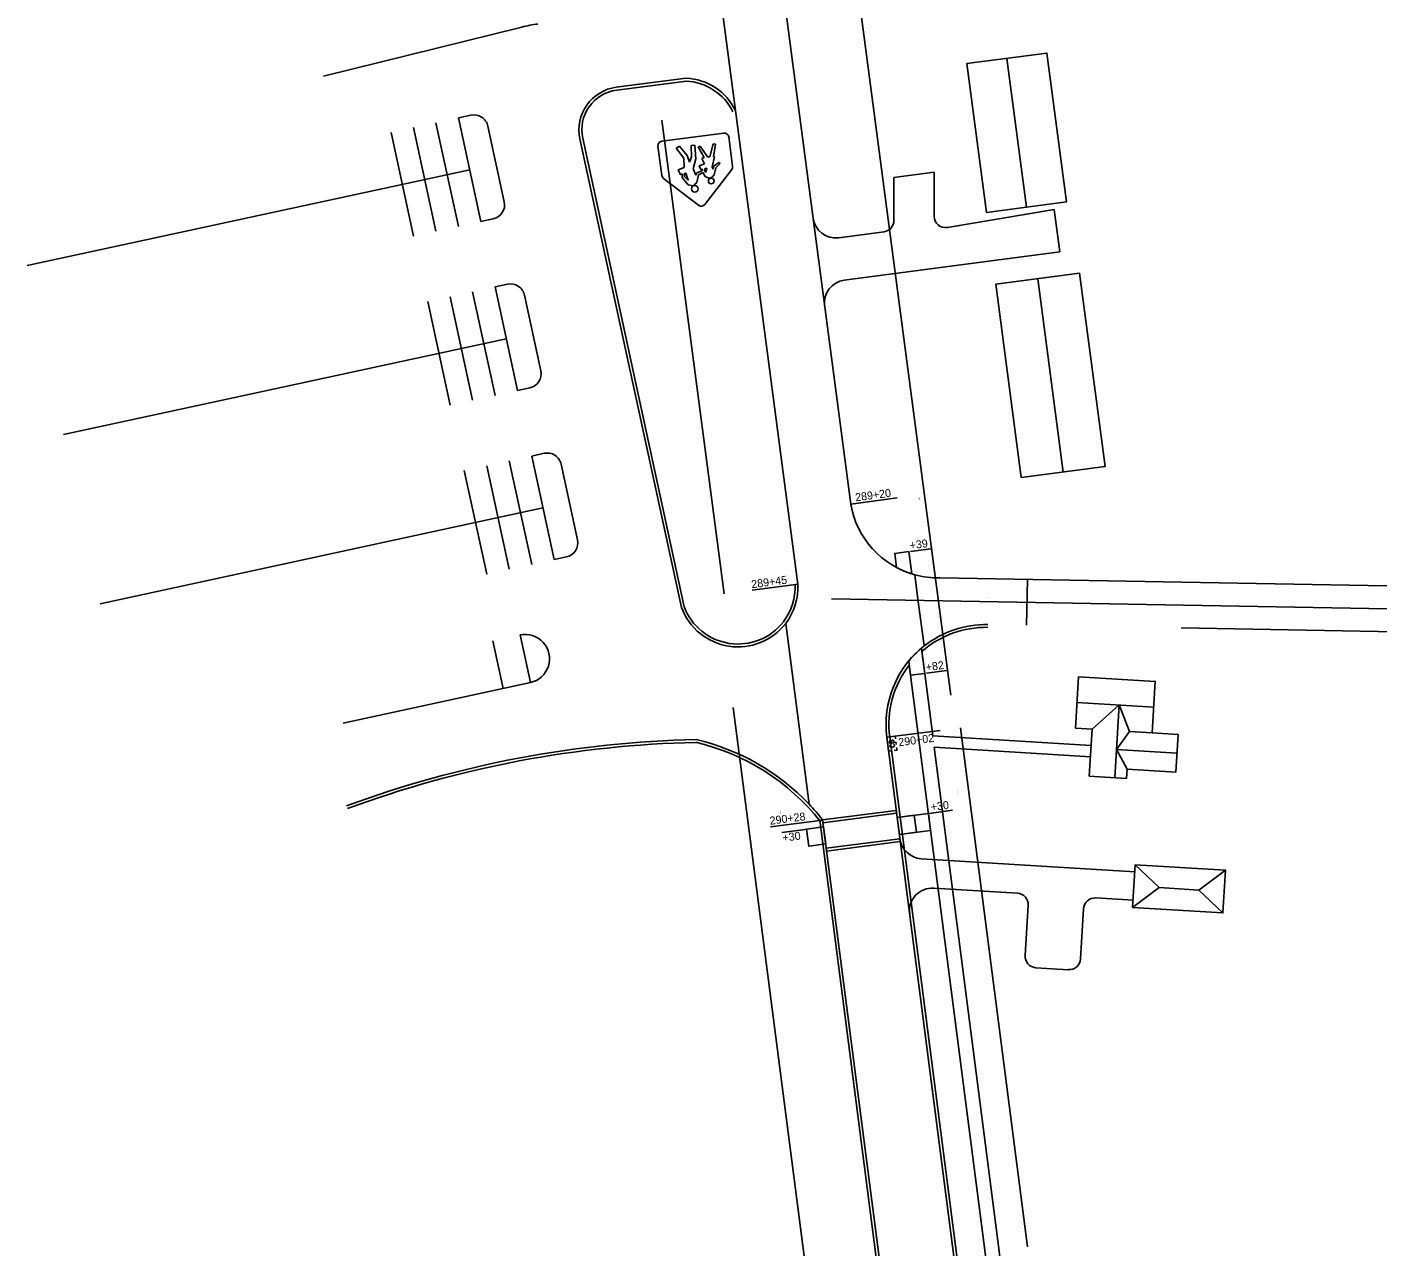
# Model space of a CAD drawing. Extents: x 107766 to 4387554, y 20109 to 1193017.
# Drawn here: x 1746574.1 to 1747046.9, y 281751.5 to 282178.4 of the extents above; entities that cross this region are included whole.
import ezdxf

# ---------------------------------------------------------------- set-up
doc = ezdxf.new("R2010")
doc.units = 0
for name, color, linetype in [('GM_X_Corporation', 7, 'Continuous'), ('GM_X_County_Road', 7, 'Continuous'), ('GM_X_State_Route', 7, 'Continuous'), ('GM_X_Township', 7, 'Continuous'), ('GM_X_US_Route', 7, 'Continuous'), ('GM_X_US_Shield', 7, 'Continuous'), ('Level 60', 7, 'Continuous'), ('Level 62', 7, 'Continuous'), ('RD_P_Text', 7, 'Continuous'), ('SC_Scratch1', 7, 'Continuous'), ('SC_Scratch10', 7, 'Continuous'), ('SC_Scratch5', 7, 'Continuous'), ('SC_Scratch8', 7, 'Continuous'), ('SH_Data', 7, 'Continuous')]:
    doc.layers.add(name, color=color, linetype=linetype)

msp = doc.modelspace()

# ---------------------------------------------------------------- linework, layer by layer
at = {"layer": 'GM_X_Corporation'}
for p, q in [((1746876.04, 281930.01), (1746875.06, 281929.89)), ((1746875.19, 281928.91), (1746875.06, 281929.89)), ((1746877.99, 281930.26), (1746877.01, 281930.14)), ((1746878.11, 281929.29), (1746877.99, 281930.26)), ((1746875.44, 281926.96), (1746875.31, 281927.93)), ((1746875.69, 281925.01), (1746875.56, 281925.98)), ((1746876.67, 281925.13), (1746875.69, 281925.01)), ((1746876.75, 281927.89), (1746876.67, 281928.58)), ((1746876.84, 281927.64), (1746876.84, 281927.64)), ((1746878.62, 281925.38), (1746877.64, 281925.26)), ((1746878.37, 281927.34), (1746878.24, 281928.31)), ((1746878.62, 281925.38), (1746878.49, 281926.36))]:
    msp.add_line(p, q, dxfattribs=at)
msp.add_lwpolyline([(1746875.96, 281928.42), (1746876.04, 281927.8), (1746877.61, 281928), (1746877.52, 281928.69)], dxfattribs=at)
for centre, radius, start, end in [((1746876.35, 281928.36), 0.388, 34.1764, 170.357), ((1746876.64, 281926.88), 0.5, 118.916, 255.7954), ((1746876.77, 281928.18), 1.8, 262.1664, 292.545), ((1746877.11, 281928.46), 0.462, 29.4104, 165.301), ((1746877.22, 281926.95), 0.5, 298.916, 75.7954)]:
    msp.add_arc(centre, radius, start, end, dxfattribs=at)
at = {"layer": 'GM_X_County_Road'}
for p, q in [((1746796.31, 282138.46), (1746818, 282141.31)), ((1746813.13, 282133.02), (1746814.32, 282137.58)), ((1746814.32, 282137.58), (1746815.08, 282137.46)), ((1746819.75, 282139.97), (1746821.09, 282129.77)), ((1746796.3, 282126.5), (1746794.96, 282136.71)), ((1746801.36, 282135.99), (1746802.48, 282136.7)), ((1746803.98, 282132.49), (1746801.36, 282135.99)), ((1746802.48, 282136.7), (1746805.12, 282133.43)), ((1746805.12, 282133.43), (1746806.05, 282131.18)), ((1746806.05, 282131.18), (1746806.66, 282132.96)), ((1746806.6, 282137.02), (1746807.86, 282137.07)), ((1746806.66, 282132.96), (1746806.6, 282137.02)), ((1746807.86, 282137.07), (1746808.23, 282132.26)), ((1746809.08, 282136.55), (1746809.69, 282136.75)), ((1746811.11, 282132.75), (1746809.08, 282136.55)), ((1746809.69, 282136.75), (1746812.24, 282133.01)), ((1746812.24, 282133.01), (1746813.13, 282133.02)), ((1746814.72, 282133), (1746813.91, 282129.5)), ((1746815.08, 282137.46), (1746814.34, 282133.06)), ((1746814.34, 282133.06), (1746814.72, 282133)), ((1746802.03, 282128.51), (1746804.14, 282129.24)), ((1746802.9, 282126.7), (1746802.03, 282128.51)), ((1746804.14, 282129.24), (1746803.98, 282132.49)), ((1746808.23, 282132.26), (1746807.3, 282128.86)), ((1746807.3, 282128.86), (1746808.18, 282126.61)), ((1746808.59, 282127.45), (1746810.35, 282128.13)), ((1746809.38, 282129.92), (1746811.25, 282130.51)), ((1746809.98, 282128.54), (1746809.38, 282129.92)), ((1746810.54, 282128.72), (1746809.98, 282128.54)), ((1746810.26, 282132.41), (1746811.11, 282132.75)), ((1746811.25, 282130.51), (1746810.26, 282132.41)), ((1746810.35, 282128.13), (1746810.54, 282128.72)), ((1746811.46, 282128.96), (1746811.23, 282128.25)), ((1746811.23, 282128.25), (1746811.7, 282127.52)), ((1746820.78, 282128.61), (1746811.37, 282116.34)), ((1746812.08, 282129.04), (1746811.46, 282128.96)), ((1746811.7, 282127.52), (1746812.08, 282129.04)), ((1746813.91, 282129.5), (1746814.29, 282128.65)), ((1746814.29, 282128.65), (1746814.52, 282129.7)), ((1746814.52, 282129.7), (1746816.24, 282131.05)), ((1746815.23, 282129.12), (1746814.65, 282126.66)), ((1746816.76, 282130.67), (1746815.23, 282129.12)), ((1746816.24, 282131.05), (1746816.76, 282130.67)), ((1746809.17, 282116.05), (1746796.9, 282125.47)), ((1746803.54, 282127.01), (1746802.9, 282126.7)), ((1746803.39, 282125.75), (1746803.54, 282127.01)), ((1746805.57, 282123.21), (1746803.39, 282125.75)), ((1746804.24, 282126.09), (1746804.25, 282127.21)), ((1746805.56, 282124.9), (1746804.24, 282126.09)), ((1746804.25, 282127.21), (1746804.72, 282127.27)), ((1746804.72, 282127.27), (1746805.56, 282124.9)), ((1746807.86, 282123.4), (1746807.84, 282123.17)), ((1746808.57, 282124.06), (1746807.86, 282123.4)), ((1746808.18, 282126.61), (1746808.59, 282127.45)), ((1746809.16, 282126.73), (1746808.57, 282124.06)), ((1746810.64, 282127.49), (1746809.16, 282126.73)), ((1746811.63, 282126.04), (1746810.64, 282127.49)), ((1746812.62, 282125.68), (1746811.63, 282126.04)), ((1746813.01, 282125.54), (1746812.62, 282125.68)), ((1746813.96, 282125.89), (1746813.01, 282125.54)), ((1746814.65, 282126.66), (1746813.96, 282125.89)), ((1746806.65, 282123.01), (1746805.57, 282123.21)), ((1746806.85, 282122.7), (1746806.65, 282123.01)), ((1746807.84, 282123.17), (1746806.85, 282122.7))]:
    msp.add_line(p, q, dxfattribs=at)
msp.add_lwpolyline([(1746804.25, 282127.21), (1746804.72, 282127.27), (1746805.56, 282124.9), (1746804.24, 282126.09), (1746804.25, 282127.21)], dxfattribs=at)
for centre, radius in [((1746813.59, 282124.56), 1), ((1746807.85, 282121.8), 1.14)]:
    msp.add_circle(centre, radius, dxfattribs=at)
for centre, start, end in [((1746796.51, 282136.91), 97.4991, 187.4991), ((1746818.2, 282139.76), 7.4991, 97.4991), ((1746819.54, 282129.56), 322.4991, 7.4991), ((1746797.85, 282126.71), 187.4991, 232.4991), ((1746810.13, 282117.29), 232.4991, 322.4991)]:
    msp.add_arc(centre, 1.56, start, end, dxfattribs=at)
at = {"layer": 'GM_X_State_Route'}
msp.add_line((1746924.27, 281985.12), (1746923.98, 281969.12), dxfattribs=at)
at = {"layer": 'GM_X_Township'}
for p, q in [((1746878.37, 281904.3), (1746852.58, 281900.97)), ((1746878.49, 281903.31), (1746852.71, 281899.97)), ((1746878.49, 281903.31), (1746878.37, 281904.3)), ((1746852.71, 281899.97), (1746852.58, 281900.97)), ((1746879.65, 281894.38), (1746853.86, 281891.05)), ((1746879.77, 281893.39), (1746853.99, 281890.06)), ((1746879.77, 281893.39), (1746879.65, 281894.38)), ((1746853.99, 281890.06), (1746853.86, 281891.05))]:
    msp.add_line(p, q, dxfattribs=at)
for points in [[(1746852.71, 281899.97), (1746878.49, 281903.31), (1746878.37, 281904.3), (1746852.58, 281900.97), (1746852.71, 281899.97)], [(1746879.65, 281894.38), (1746853.86, 281891.05), (1746853.99, 281890.06), (1746879.77, 281893.39), (1746879.65, 281894.38)]]:
    msp.add_lwpolyline(points, dxfattribs=at)
at = {"layer": 'GM_X_US_Route'}
for p, q in [((1746877.84, 281994.23), (1746882.8, 281994.87)), ((1746878.48, 281989.27), (1746877.84, 281994.23)), ((1746883.81, 281987.06), (1746882.8, 281994.87)), ((1746888.31, 281952.24), (1746887.16, 281961.09)), ((1746883.35, 281951.6), (1746882.71, 281956.56)), ((1746883.35, 281951.6), (1746888.31, 281952.24)), ((1746878.69, 281901.82), (1746889.59, 281903.23)), ((1746879.45, 281895.87), (1746878.69, 281901.82)), ((1746885.4, 281896.64), (1746884.64, 281902.59)), ((1746890.36, 281897.28), (1746889.59, 281903.23)), ((1746852.9, 281898.49), (1746846.95, 281897.72)), ((1746847.72, 281891.77), (1746846.95, 281897.72)), ((1746853.67, 281892.54), (1746852.9, 281898.49)), ((1746879.45, 281895.87), (1746890.36, 281897.28)), ((1746853.67, 281892.54), (1746847.72, 281891.77))]:
    msp.add_line(p, q, dxfattribs=at)
for points in [[(1746883.81, 281987.06), (1746882.8, 281994.87), (1746877.84, 281994.23), (1746878.48, 281989.27)], [(1746882.71, 281956.56), (1746882.88, 281955.18), (1746883.35, 281951.6), (1746888.31, 281952.24), (1746887.32, 281959.9), (1746887.16, 281961.09)], [(1746884.64, 281902.59), (1746878.69, 281901.82), (1746879.45, 281895.87), (1746885.4, 281896.64), (1746884.64, 281902.59)], [(1746853.67, 281892.54), (1746852.9, 281898.49), (1746846.95, 281897.72), (1746847.72, 281891.77), (1746853.67, 281892.54)]]:
    msp.add_lwpolyline(points, dxfattribs=at)
for centre, radius, start, end in [((1746893, 282016.69), 31.02, 242.0974, 252.7684), ((1746909.77, 281934.37), 35, 130.2383, 140.6518)]:
    msp.add_arc(centre, radius, start, end, dxfattribs=at)
at = {"layer": 'GM_X_US_Shield'}
for p, q in [((1746807.44, 282628.31), (1746897.44, 281944.65)), ((1746796.32, 282145.83), (1746818.14, 281980.05)), ((1746900.85, 281933.22), (1746924.32, 281751.52)), ((1746900.85, 281933.22), (1746924.32, 281751.52))]:
    msp.add_line(p, q, dxfattribs=at)
msp.add_lwpolyline([(1746821.28, 281940.31), (1746846.89, 281742.05), (1746853.99, 281676.73), (1746855.07, 281648), (1746854.92, 281623.09), (1746854.78, 281621.07)], dxfattribs=at)
at = {"layer": 'Level 60'}
for p, q in [((1746747.36, 282178.44), (1746677.86, 282161.26)), ((1746780.38, 282157.36), (1746804.81, 282160.53)), ((1746725.13, 282146.64), (1746729.48, 282147.58)), ((1746709.4, 282143.23), (1746717.26, 282106.98)), ((1746717.27, 282144.93), (1746725.12, 282108.68)), ((1746725.13, 282146.64), (1746732.99, 282110.39)), ((1746735.43, 282143.75), (1746741.16, 282117.28)), ((1746701.54, 282141.53), (1746709.39, 282105.28)), ((1746803.18, 281975.33), (1746767.65, 282139.31)), ((1746729.06, 282128.51), (1746574.14, 282094.95)), ((1746877.53, 282125.78), (1746891.57, 282127.63)), ((1746877.55, 282110.76), (1746877.53, 282125.78)), ((1746891.59, 282112.22), (1746891.57, 282127.63)), ((1746896.26, 282108.28), (1746933.6, 282114.63)), ((1746935.56, 282099.77), (1746933.6, 282114.63)), ((1746732.99, 282110.39), (1746737.33, 282111.33)), ((1746874.08, 282106.79), (1746858.21, 282104.7)), ((1746860.17, 282089.85), (1746935.56, 282099.77)), ((1746730.09, 282085.77), (1746737.94, 282049.52)), ((1746737.95, 282087.48), (1746742.3, 282088.42)), ((1746737.95, 282087.48), (1746745.81, 282051.23)), ((1746714.36, 282082.36), (1746722.21, 282046.11)), ((1746722.22, 282084.07), (1746730.07, 282047.82)), ((1746748.24, 282084.59), (1746753.98, 282058.11)), ((1746741.88, 282069.35), (1746586.96, 282035.79)), ((1746745.81, 282051.23), (1746750.15, 282052.17)), ((1746750.77, 282028.31), (1746755.12, 282029.26)), ((1746735.04, 282024.91), (1746742.89, 281988.66)), ((1746742.9, 282026.61), (1746750.76, 281990.36)), ((1746750.77, 282028.31), (1746758.62, 281992.06)), ((1746761.06, 282025.43), (1746766.8, 281998.95)), ((1746727.17, 282023.2), (1746735.03, 281986.95)), ((1746754.7, 282010.19), (1746599.78, 281976.63)), ((1746758.62, 281992.06), (1746762.97, 281993.01)), ((1746740.81, 281947), (1746737.2, 281963.65)), ((1746750.3, 281949.05), (1746746.69, 281965.71)), ((1746750.3, 281949.05), (1746684.73, 281934.85)), ((1746961.83, 281882.84), (1746887.1, 281887.39)), ((1746920.79, 281875.32), (1746891.46, 281877.11)), ((1746961.22, 281872.85), (1746948.15, 281873.65)), ((1746924.53, 281871.08), (1746923.46, 281853.49)), ((1746942.84, 281852.31), (1746943.91, 281869.9)), ((1746927.21, 281849.26), (1746938.6, 281848.56))]:
    msp.add_line(p, q, dxfattribs=at)
for centre, radius, start, end in [((1746759.36, 282129.9), 50, 97.4048, 103.8878), ((1746782.31, 282142.48), 15, 97.4048, 192.2244), ((1746803.87, 282140.23), 20.32, 26.2452, 87.3452), ((1746730.54, 282142.69), 5, 12.2244, 102.2244), ((1746736.28, 282116.22), 5, 282.2244, 12.2244), ((1746857.17, 282112.63), 8, 187.4991, 277.4991), ((1746873.55, 282110.76), 4, 277.4991, 0.0921), ((1746895.59, 282112.22), 4, 180.0921, 279.6487), ((1746743.36, 282083.53), 5, 12.2244, 102.2244), ((1746861.21, 282081.92), 8, 97.4991, 187.4991), ((1746749.09, 282057.05), 5, 282.2244, 12.2244), ((1746756.18, 282024.37), 5, 12.2244, 102.2244), ((1746761.91, 281997.89), 5, 282.2244, 12.2244), ((1746822.98, 281982.62), 21.1, 200.2353, 322.2761), ((1746748.49, 281957.38), 8.52, 282.2244, 102.2244), ((1746816.41, 281552.7), 376.49, 91.2338, 110.2783), ((1746790.14, 281851.51), 79.69, 43.6207, 76.8305), ((1746887.58, 281895.38), 8, 187.36, 266.5119), ((1746890.98, 281869.12), 8, 86.5119, 187.36), ((1746920.54, 281871.33), 4, 356.5119, 86.5119), ((1746947.9, 281869.66), 4, 86.5119, 176.5119), ((1746927.45, 281853.25), 4, 176.5119, 266.5119), ((1746938.85, 281852.56), 4, 266.5119, 356.5119)]:
    msp.add_arc(centre, radius, start, end, dxfattribs=at)
at = {"layer": 'RD_P_Text'}
for p, q in [((1746890.51, 281995.87), (1746883.32, 281994.94)), ((1746896.07, 281953.25), (1746888.94, 281952.33)), ((1746898.01, 281904.33), (1746890.71, 281903.38)), ((1746845.6, 281897.54), (1746838.3, 281896.59))]:
    msp.add_line(p, q, dxfattribs=at)
for points in [[(1746890.71, 281903.38), (1746889.59, 281903.23)], [(1746845.6, 281897.54), (1746846.95, 281897.72)]]:
    msp.add_lwpolyline(points, dxfattribs=at)
at = {"layer": 'SC_Scratch1'}
for p, q in [((1746946.54, 281927.06), (1746891.12, 281930.44)), ((1746946.3, 281923.07), (1746891.64, 281926.4))]:
    msp.add_line(p, q, dxfattribs=at)
for points in [[(1746883.35, 281951.6), (1746909.45, 281749.49), (1746916.86, 281681.32), (1746918.07, 281648.99), (1746917.9, 281620.7), (1746915, 281579.26), (1746908.98, 281517.15)], [(1746888.31, 281952.24), (1746891.12, 281930.44)], [(1746891.64, 281926.4), (1746914.42, 281750.08), (1746921.85, 281681.68), (1746923.07, 281649.07), (1746922.9, 281620.51), (1746919.98, 281578.85), (1746912.65, 281503.19), (1746902.98, 281420.91)]]:
    msp.add_lwpolyline(points, dxfattribs=at)
at = {"layer": 'SC_Scratch10'}
for p, q in [((1746814.55, 282206.55), (1746822.09, 282149.22)), ((1746847.83, 281906.49), (1746839.67, 281969.71))]:
    msp.add_line(p, q, dxfattribs=at)
for points in [[(1746781.67, 282624.92), (1746862.41, 282011.49)], [(1746822.09, 282149.22), (1746843.92, 281983.44)], [(1746884.83, 281986.76), (1746885.96, 281978.22), (1746888.07, 281961.83)], [(1746893.6, 281985.67), (1747147.79, 281981.09), (1747577.79, 281967.01), (1747742.74, 281960.98)], [(1746978.01, 281968.15), (1747147.39, 281965.09), (1747577.24, 281951.02), (1747742.15, 281944.99)], [(1746875.06, 281929.89), (1746898.53, 281748.19), (1746905.88, 281680.52), (1746907.07, 281648.82), (1746906.91, 281621.12), (1746904.04, 281580.18), (1746896.74, 281504.9), (1746809.36, 280761.28), (1746739.33, 280161.48), (1746680.46, 279666.62)], [(1746852.58, 281900.97), (1746872.71, 281745.12), (1746879.94, 281678.63), (1746881.07, 281648.41), (1746880.91, 281622.11), (1746880.71, 281619.25)]]:
    msp.add_lwpolyline(points, dxfattribs=at)
for centre, radius, start, end in [((1746893, 282016.69), 31.02, 189.6442, 254.7419), ((1746893.44, 282020.27), 34.6, 255.5934, 270.2612), ((1746822.94, 281982.41), 21, 322.7855, 2.8132), ((1746910.11, 281933.36), 36.01, 89.5399, 127.7372), ((1746909.77, 281934.37), 35, 128.3097, 187.36), ((1746790.78, 281852.62), 78.46, 38.0353, 43.3526)]:
    msp.add_arc(centre, radius, start, end, dxfattribs=at)
at = {"layer": 'SC_Scratch5'}
for p, q in [((1746780.51, 282156.36), (1746804.94, 282159.54)), ((1746804.16, 281975.54), (1746768.63, 282139.52))]:
    msp.add_line(p, q, dxfattribs=at)
for points in [[(1746876.05, 281930.01), (1746899.52, 281748.31), (1746906.88, 281680.59), (1746908.07, 281648.83), (1746907.91, 281621.08), (1746905.03, 281580.1), (1746899.02, 281518.12)], [(1746851.59, 281900.84), (1746871.72, 281745), (1746878.94, 281678.55), (1746880.07, 281648.39), (1746879.91, 281622.14), (1746879.72, 281619.45)]]:
    msp.add_lwpolyline(points, dxfattribs=at)
for centre, radius, start, end in [((1746803.87, 282140.23), 19.32, 26.2452, 87.3452), ((1746782.31, 282142.48), 14, 97.4048, 192.2244), ((1746822.94, 281982.41), 20, 322.7855, 2.8132), ((1746822.98, 281982.62), 20.1, 200.2353, 322.2761), ((1746909.77, 281934.37), 34, 88.9674, 131.3344), ((1746909.77, 281934.37), 34, 142.2608, 187.36), ((1746816.41, 281552.7), 375.49, 91.2338, 110.2783), ((1746790.78, 281852.62), 77.46, 38.0353, 77.0986)]:
    msp.add_arc(centre, radius, start, end, dxfattribs=at)
at = {"layer": 'SC_Scratch8'}
for p, q in [((1746923.89, 282115.38), (1746917.03, 282167.47)), ((1746927.86, 282090.36), (1746936.77, 282022.67)), ((1746968.46, 281940.45), (1746941.6, 281942.09)), ((1746956.35, 281941.19), (1746946.89, 281932.75)), ((1746954.8, 281915.75), (1746956.35, 281941.19)), ((1746959.97, 281931.95), (1746956.35, 281941.19)), ((1746946.89, 281932.75), (1746945.89, 281916.29)), ((1746955.4, 281925.58), (1746959.97, 281931.95)), ((1746967.91, 281931.47), (1746976.99, 281930.91)), ((1746976.99, 281930.91), (1746976.18, 281917.67)), ((1746976.59, 281924.29), (1746955.4, 281925.58)), ((1746955.4, 281925.58), (1746959.16, 281918.71)), ((1746958.96, 281915.49), (1746945.89, 281916.29)), ((1746959.16, 281918.71), (1746958.96, 281915.49)), ((1746976.18, 281917.67), (1746959.16, 281918.71)), ((1746970.37, 281877.28), (1746961.98, 281885.3)), ((1746984.28, 281876.44), (1746993.58, 281883.38)), ((1746970.37, 281877.28), (1746961.06, 281870.34)), ((1746977.32, 281876.86), (1746970.37, 281877.28)), ((1746984.28, 281876.44), (1746977.32, 281876.86)), ((1746984.28, 281876.44), (1746992.67, 281868.42))]:
    msp.add_line(p, q, dxfattribs=at)
for points in [[(1746909.88, 282113.54), (1746903.02, 282165.62), (1746931.05, 282169.31), (1746937.9, 282117.23)], [(1746922.09, 282020.74), (1746913.18, 282088.42), (1746942.53, 282092.29), (1746951.44, 282024.61)], [(1746961.06, 281870.34), (1746961.98, 281885.3), (1746993.58, 281883.38), (1746992.67, 281868.42)]]:
    msp.add_lwpolyline(points, close=True, dxfattribs=at)
msp.add_lwpolyline([(1746959.97, 281931.95), (1746967.91, 281931.47), (1746969.01, 281949.44), (1746942.14, 281951.08), (1746941.05, 281933.1), (1746946.89, 281932.75)], dxfattribs=at)
at = {"layer": 'SH_Data'}
for p, q in [((1746878.68, 282013.64), (1746864.26, 282011.75)), ((1746842.29, 281983.23), (1746827.89, 281981.33)), ((1746893.74, 281932.3), (1746875.06, 281929.89)), ((1746852.59, 281900.92), (1746834.32, 281898.56))]:
    msp.add_line(p, q, dxfattribs=at)
for points in [[(1746864.26, 282011.75), (1746862.41, 282011.5)], [(1746842.29, 281983.23), (1746843.92, 281983.44)], [(1746855.68, 281978.35), (1747147.59, 281973.09), (1747577.52, 281959.02), (1747742.44, 281952.99)]]:
    msp.add_lwpolyline(points, dxfattribs=at)

# ---------------------------------------------------------------- texts
at = {"layer": 'GM_X_US_Shield'}
for s, p in [('PAD LANDING', (1746886.2, 282013.79)), ('DESIGN G', (1746886.41, 282013.82)), ('DESIGN G', (1746893.75, 281957.03)), ('DESIGN G', (1746899.67, 281911.15)), ('PAD LANDING', (1746837.6, 281904.07)), ('DESIGN G', (1746837.81, 281904.09))]:
    msp.add_text(s, height=0.14, rotation=277.36, dxfattribs=at).set_placement(p)
at = {"layer": 'Level 62'}
msp.add_text('LANDON RD', height=0.14, rotation=358.9674, dxfattribs=at).set_placement((1746909.72, 281978.78))
at = {"layer": 'RD_P_Text'}
for s, p in [('+39', (1746883.24, 281995.62)), ('+82', (1746888.87, 281953)), ('+30', (1746890.63, 281904.06)), ('+30', (1746838.73, 281893.3))]:
    msp.add_text(s, height=2.8, rotation=7.4076, dxfattribs=at).set_placement(p)
at = {"layer": 'SC_Scratch10'}
for s, rotation, p in [('289+20', 7.4991, (1746864.17, 282012.44)), ('289+45', 7.4991, (1746827.81, 281982.03)), ('290+02', 7.36, (1746879.26, 281926.71)), ('290+28', 7.36, (1746834.24, 281899.26))]:
    msp.add_text(s, height=2.8, rotation=rotation, dxfattribs=at).set_placement(p)

doc.saveas('drawing.dxf')
